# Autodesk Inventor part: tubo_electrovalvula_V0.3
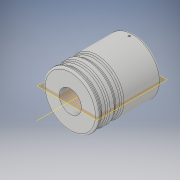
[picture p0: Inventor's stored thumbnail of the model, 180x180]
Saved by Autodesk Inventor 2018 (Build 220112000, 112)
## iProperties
Created: 2018-09
Part Number: tubo_electrovalvula_V0.3
Material: Generic
Document SubType Name: Modeling
Designer: Gordillo
Density: 1 g/cm^3
Appearance: Default
Author: Gordillo
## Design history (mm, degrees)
sketch "Sketch1"
  geometry: C1 r 55 at (0, 0); 1 further point
  constraints: 1 centre point, 1 coincident
  dimensions: "d0" = 110 diameter of C1
extrude "Extrusion1" new body sketch "Sketch1" distance "d1" = 130; taper "d2" = 0 deg
sketch "Sketch2"
  geometry: L1 (55, 130)-(-55, 130) reference; L2 (-55, 0)-(55, 0) reference; L3 (55, 0)-(55, 130) reference; L4 (55, 80)-(52, 80); L5 (52, 80)-(52, 92); L6 (52, 92)-(55, 92); L7 (55, 92)-(55, 80); L8 (55, 108)-(52, 108); L9 (52, 108)-(52, 120); L10 (52, 120)-(55, 120); L11 (55, 120)-(55, 108); L12 (0, -30)-(0, 180) reference; 1 further point
  constraints: 16 end point, 4 parallel, 2 horizontal, 2 perpendicular, 2 point on line
  dimensions: "d3" = 3 distance of L5.end L6.end; "d4" = 12 distance of L4.end L5.end; "d5" = 80 distance between parallel lines of L2 L4; "d6" = 3 distance of L9.end L10.end; "d7" = 12 distance of L8.end L9.end; "d8" = 16 distance between parallel lines of L8 L6
revolve "Revolution1" sketch "Sketch2" stored, may be unused: angle "d9" = 90 deg
fillet "Fillet1" dims "d10" = 4
sketch "Sketch3"
  geometry: C1 r 22.5 at (0, 0); 1 further point
  constraints: 1 centre point, 1 coincident
  dimensions: "d11" = 45 diameter of C1
extrude "Extrusion2" cut sketch "Sketch3" distance "d12" = 110; taper "d13" = 0 deg
fillet "Fillet2" dims "d14" = 4
workplane "Work Plane1"
sketch "Sketch4"
  geometry: L1 (0, -26)-(0, 156) reference; L2 (51, 0)-(-51, 0) reference; 2 further points
  constraints: 1 point on line
  dimensions: "d15" = 30 distance from line of L2 point (0, 30)
hole "Hole1" sketch "Sketch4" at (0, 30) diameter "d16" = 12; stored, may be unused: countersink angle "d20" = 90 deg, drill point angle "d22" = 118 deg; dims "d17" = 6, "d18" = 14, "d19" = 4, "d21" = 8
thread "Thread1" dims "d23" = 10, "d24" = 0
sketch "Sketch5"
  geometry: L1 (-55, 4)-(55, 4) reference; L2 (51, 0)-(-51, 0) reference; L3 (-55, 4)-(-55, 76.127) reference; L4 (55, 4)-(55, 76.127) reference; L5 (0, -16.22)-(0, 91.518) reference; C1 r 2 at (0, 10); A1 r 4 centre (51, 4) between (51, 0) and (55, 4) reference; A2 r 4 centre (-51, 4) between (-55, 4) and (-51, 0) reference; 1 further point
  constraints: 1 centre point, 1 point on line
  dimensions: "d25" = 4 diameter of C1; "d26" = 10 distance from line of L2 C1.centre
extrude "Extrusion3" cut sketch "Sketch5" extent not by distance; stored distance "d27" = 200; taper "d28" = 0 deg
body "Solid1"
node "Projected Loop1"
node "Projected Loop2"
